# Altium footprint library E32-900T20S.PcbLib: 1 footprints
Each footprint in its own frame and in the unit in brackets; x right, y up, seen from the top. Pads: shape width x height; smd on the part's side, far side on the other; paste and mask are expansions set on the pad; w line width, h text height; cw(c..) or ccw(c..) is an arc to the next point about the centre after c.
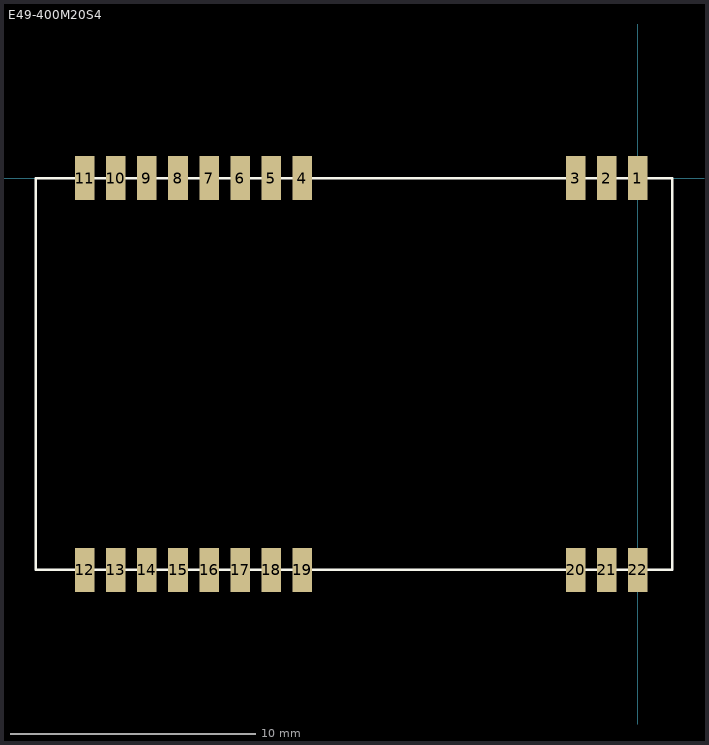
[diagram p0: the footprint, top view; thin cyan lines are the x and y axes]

## E49-400M20S4 [mm]
pads (22):
  rect 0.8x1.8 smd: 1(0,0) 2(-1.27,0) 3(-2.54,0) 4(-13.71,0) 5(-14.98,0) 6(-16.25,0) 7(-17.52,0) 8(-18.79,0) 9(-20.06,0) 10(-21.33,0) 11(-22.6,0) 12(-22.6,-16) 13(-21.33,-16) 14(-20.06,-16) 15(-18.79,-16) 16(-17.52,-16) 17(-16.25,-16) 18(-14.98,-16) 19(-13.71,-16) 20(-2.54,-16) 21(-1.27,-16) 22(0,-16)
Top Overlay:
  lines w0.1: -24.6,-16 1.4,-16 1.4,0 -24.6,0 -24.6,-16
